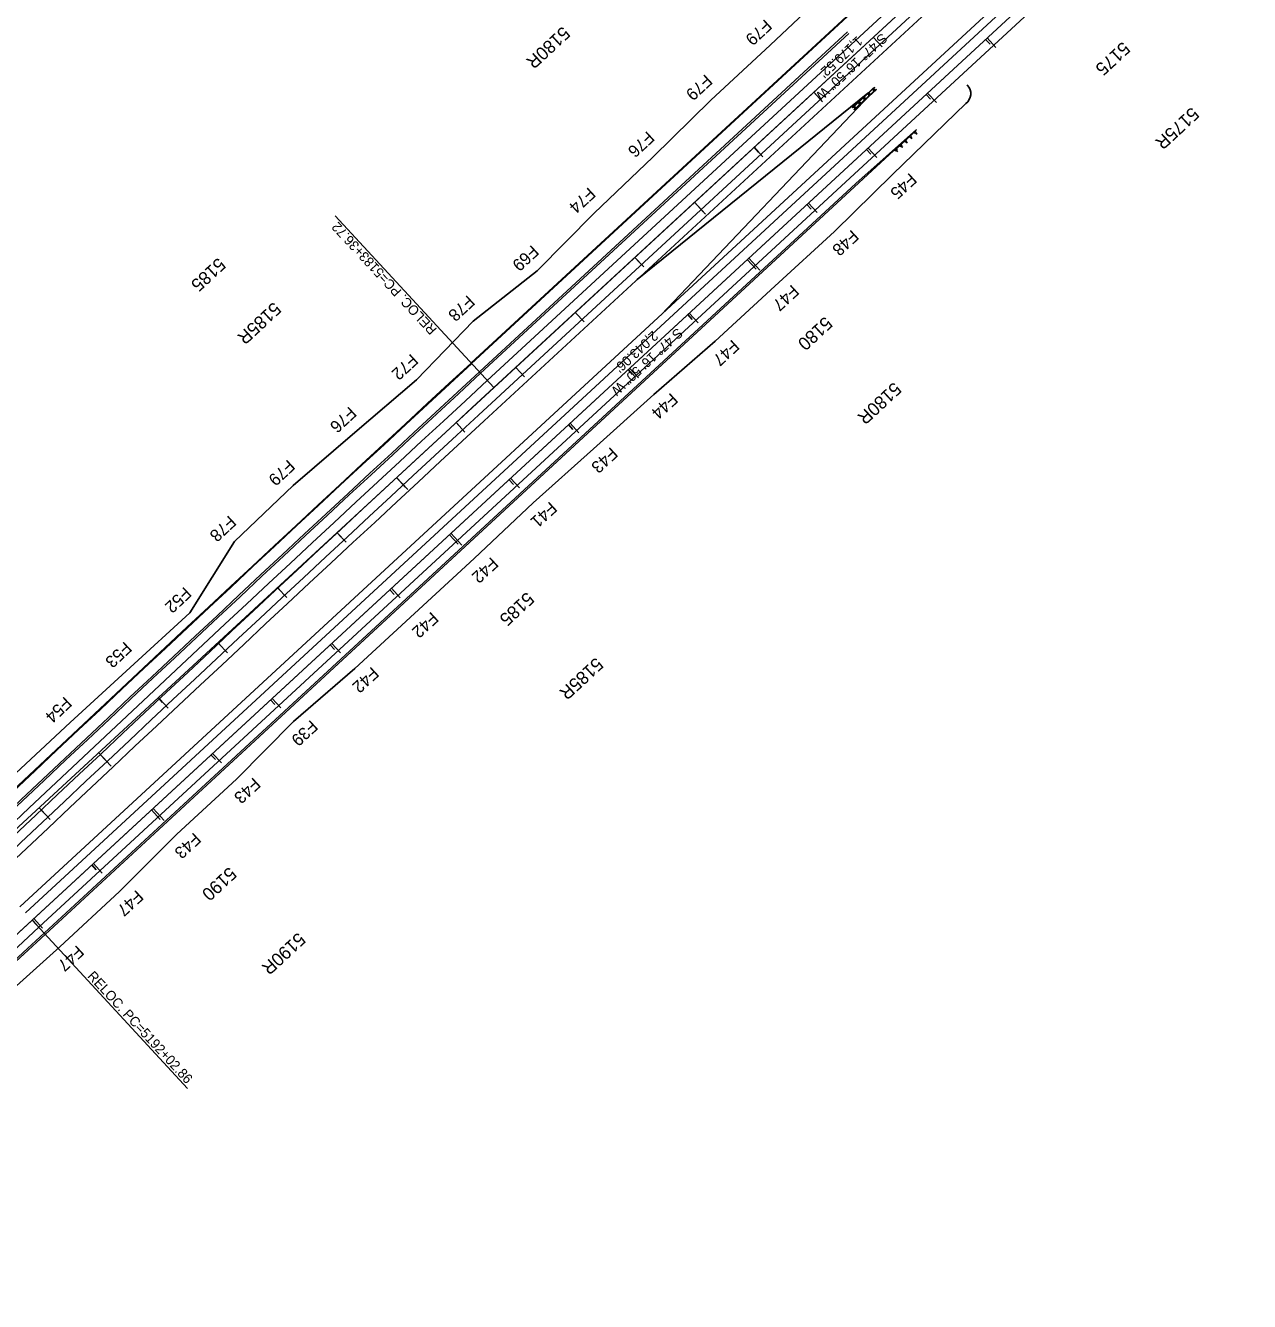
# Model space of a CAD drawing. Extents: x 2160877 to 2175861, y 601747 to 617724.
# Drawn here: x 2170763 to 2172272, y 611848 to 613421 of the extents above; entities that cross this region are included whole.
import ezdxf

# ---------------------------------------------------------------- set-up
doc = ezdxf.new("R2010")
doc.units = 0
for name, color, linetype in [('RD_HC_Cl', 7, 'Continuous'), ('RD_HC_CL_Rel', 7, 'Continuous'), ('RD_HC_Data_Rel', 7, 'Continuous'), ('RD_HC_Data_Tic', 7, 'Continuous'), ('RD_HC_Data_Tic_Rel', 7, 'Continuous'), ('RD_HC_TX_Rel_Sta50', 7, 'Continuous'), ('RD_HC_TX_Rel_StaOther', 7, 'Continuous'), ('RD_HC_TX_StaOther', 7, 'Continuous'), ('RD_PD_CstnLmt', 7, 'Continuous'), ('RD_PD_CstnLmt_TX', 7, 'Continuous'), ('RD_PD_Final_LnLine', 7, 'Continuous'), ('RD_PD_Final_TrvlWay', 7, 'Continuous'), ('RD_PD_GR', 7, 'Continuous'), ('RD_PD_MedBWall', 7, 'Continuous')]:
    doc.layers.add(name, color=color, linetype=linetype)

msp = doc.modelspace()

# ---------------------------------------------------------------- linework, layer by layer
at = {"layer": 'RD_HC_Cl'}
for p, q in [((2172207.3, 613775.1), (2163672.2, 605893.8)), ((2172272.5, 613704.6), (2163737.4, 605823.3))]:
    msp.add_line(p, q, dxfattribs=at)
at = {"layer": 'RD_HC_CL_Rel'}
for p, q in [((2172207.3, 613775.1), (2171340.7, 612974.9)), ((2172272.5, 613704.6), (2170771.4, 612318.6))]:
    msp.add_line(p, q, dxfattribs=at)
for centre, radius in [((2222221.5, 557873.6), 75000), ((2219616.9, 559421.3), 72000)]:
    msp.add_arc(centre, radius, 132.719474, 134.517591, dxfattribs=at)
at = {"layer": 'RD_HC_Data_Rel'}
for p, q in [((2171340.7, 612974.9), (2171145.2, 613186.7)), ((2170771.4, 612318.6), (2170963.2, 612110.9))]:
    msp.add_line(p, q, dxfattribs=at)
at = {"layer": 'RD_HC_Data_Tic'}
for p, q in [((2171808.5, 613406.9), (2171814, 613401)), ((2171947.1, 613404.2), (2171952.6, 613398.3)), ((2171735.1, 613339.1), (2171740.5, 613333.2)), ((2171873.7, 613336.4), (2171879.1, 613330.5)), ((2171661.6, 613271.2), (2171667, 613265.3)), ((2171800.2, 613268.5), (2171805.6, 613262.7)), ((2171588.1, 613203.4), (2171599, 613191.6)), ((2171726.7, 613200.7), (2171732.2, 613194.8)), ((2171514.7, 613135.5), (2171520.1, 613129.7)), ((2171653.3, 613132.8), (2171664.1, 613121.1)), ((2171441.2, 613067.7), (2171446.6, 613061.8)), ((2171579.8, 613065), (2171585.2, 613059.1)), ((2171367.7, 612999.9), (2171373.2, 612994)), ((2171506.3, 612997.2), (2171511.8, 612991.3)), ((2171294.3, 612932), (2171299.7, 612926.1)), ((2171432.9, 612929.3), (2171438.3, 612923.4)), ((2171220.8, 612864.2), (2171231.6, 612852.4)), ((2171359.4, 612861.5), (2171364.8, 612855.6)), ((2171147.3, 612796.3), (2171152.7, 612790.5)), ((2171285.9, 612793.6), (2171296.8, 612781.9)), ((2171073.9, 612728.5), (2171079.3, 612722.6)), ((2171212.4, 612725.8), (2171217.9, 612719.9)), ((2171000.4, 612660.7), (2171005.8, 612654.8)), ((2171139, 612658), (2171144.4, 612652.1)), ((2170926.9, 612592.8), (2170932.3, 612586.9)), ((2171065.5, 612590.1), (2171070.9, 612584.2)), ((2170853.4, 612525), (2170864.3, 612513.2)), ((2170992, 612522.3), (2170997.5, 612516.4)), ((2170780, 612457.1), (2170785.4, 612451.3)), ((2170918.6, 612454.4), (2170929.4, 612442.7)), ((2170845.1, 612386.6), (2170850.5, 612380.7)), ((2170771.6, 612318.8), (2170777.1, 612312.9))]:
    msp.add_line(p, q, dxfattribs=at)
at = {"layer": 'RD_HC_Data_Tic_Rel'}
for p, q in [((2171808.5, 613406.9), (2171819.4, 613395.1)), ((2171949, 613406), (2171959.9, 613394.2)), ((2171735.1, 613339.1), (2171745.9, 613327.3)), ((2171875.6, 613338.1), (2171886.4, 613326.4)), ((2171661.6, 613271.2), (2171672.5, 613259.5)), ((2171802.1, 613270.3), (2171813, 613258.5)), ((2171588.1, 613203.4), (2171601.7, 613188.7)), ((2171728.6, 613202.5), (2171739.5, 613190.7)), ((2171514.7, 613135.5), (2171525.5, 613123.8)), ((2171655.2, 613134.6), (2171668.7, 613119.9)), ((2171441.2, 613067.7), (2171452.1, 613055.9)), ((2171581.7, 613066.8), (2171592.6, 613055)), ((2171367.7, 612999.9), (2171378.6, 612988.1)), ((2171508.2, 612998.9), (2171519.1, 612987.2)), ((2171294.3, 612932), (2171305.1, 612920.2)), ((2171434.8, 612931.1), (2171445.6, 612919.3)), ((2171220.9, 612864), (2171234.5, 612849.4)), ((2171361.3, 612863.2), (2171372.2, 612851.5)), ((2171147.6, 612796), (2171158.5, 612784.3)), ((2171287.8, 612795.4), (2171301.4, 612780.7)), ((2171074.5, 612727.8), (2171085.4, 612716.1)), ((2171214.4, 612727.6), (2171225.2, 612715.8)), ((2171001.4, 612659.6), (2171012.3, 612647.9)), ((2171140.9, 612659.7), (2171151.7, 612648)), ((2170928.4, 612591.3), (2170939.3, 612579.6)), ((2171067.4, 612591.9), (2171078.3, 612580.1)), ((2170855.4, 612522.8), (2170869.1, 612508.2)), ((2170994, 612524), (2171004.8, 612512.3)), ((2170782.6, 612454.3), (2170793.6, 612442.6)), ((2170920.5, 612456.2), (2170934.1, 612441.5)), ((2170847, 612388.4), (2170857.9, 612376.6)), ((2170773.5, 612320.5), (2170784.4, 612308.8))]:
    msp.add_line(p, q, dxfattribs=at)
at = {"layer": 'RD_PD_CstnLmt'}
for p, q in [((2171754.2, 613465.7), (2171681.6, 613397)), ((2171681.6, 613397), (2171608.1, 613329.1)), ((2171924.2, 613348.1), (2171924.8, 613347.4)), ((2171608.1, 613329.1), (2171536.7, 613259)), ((2171832.4, 613237.5), (2171922.9, 613325.2)), ((2171536.7, 613259), (2171464.3, 613190.1)), ((2171832.4, 613237.5), (2171760.9, 613167.5)), ((2171464.3, 613190.1), (2171394.1, 613118.7)), ((2171760.9, 613167.5), (2171687.3, 613099.8)), ((2171394.1, 613118.7), (2171315.1, 613056.8)), ((2171687.3, 613099.8), (2171613.7, 613032.1)), ((2171315.1, 613056.8), (2171245.5, 612984.7)), ((2171613.7, 613032.1), (2171538.1, 612966.6)), ((2171245.5, 612984.7), (2171169.4, 612919.6)), ((2171538.1, 612966.6), (2171463.8, 612899.6)), ((2171169.4, 612919.6), (2171093.5, 612854.2)), ((2171463.8, 612899.6), (2171389.4, 612832.8)), ((2171093.5, 612854.2), (2171021, 612785.2)), ((2171389.4, 612832.8), (2171316.6, 612764.2)), ((2171021, 612785.2), (2170966, 612697.4)), ((2171316.6, 612764.2), (2171242.9, 612696.6)), ((2170966, 612697.4), (2170892.2, 612629.8)), ((2171242.9, 612696.6), (2171169.4, 612628.9)), ((2170892.2, 612629.8), (2170818.5, 612562.2)), ((2171169.4, 612628.9), (2171093.9, 612563.2)), ((2170818.5, 612562.2), (2170745.3, 612493.8)), ((2171093.9, 612563.2), (2171023.3, 612492.3)), ((2171023.3, 612492.3), (2170949.9, 612424.4)), ((2170949.9, 612424.4), (2170879, 612353.7)), ((2170879, 612353.7), (2170805.7, 612285.7)), ((2170805.7, 612285.7), (2170731.3, 612218.9))]:
    msp.add_line(p, q, dxfattribs=at)
msp.add_arc((2171913.8, 613337.2), 15, 307.2254, 42.7195, dxfattribs=at)
at = {"layer": 'RD_PD_Final_LnLine'}
for p, q in [((2172199.2, 613784), (2171332.6, 612983.8)), ((2172215.5, 613766.3), (2171348.9, 612966.1)), ((2172264.3, 613713.4), (2170763.3, 612327.4)), ((2172224.1, 613643.7), (2170779.6, 612309.8)), ((2171802, 613337.9), (2171517.6, 613108.3)), ((2171804.3, 613335.4), (2171547.4, 613065))]:
    msp.add_line(p, q, dxfattribs=at)
for centre, radius in [((2222221.5, 557873.6), 75012), ((2222221.5, 557873.6), 74988), ((2219616.9, 559421.3), 71988)]:
    msp.add_arc(centre, radius, 132.719474, 134.517591, dxfattribs=at)
at = {"layer": 'RD_PD_Final_TrvlWay'}
for p, q in [((2172222.2, 613759), (2171355.7, 612958.8)), ((2172257.5, 613720.8), (2170756.5, 612334.7)), ((2171776.7, 613413.4), (2171322.9, 612994.3)), ((2171778.3, 613411.6), (2171324.5, 612992.6)), ((2171787.2, 613226.6), (2171862, 613293)), ((2171787.2, 613226.6), (2170786.4, 612302.4))]:
    msp.add_line(p, q, dxfattribs=at)
for centre, radius in [((2222220.1, 557875.1), 75024.3), ((2222220.1, 557875.1), 75022), ((2222221.5, 557873.6), 74978), ((2219616.9, 559421.3), 71978)]:
    msp.add_arc(centre, radius, 132.719474, 134.517591, dxfattribs=at)
at = {"layer": 'RD_PD_GR'}
for p, q in [((2171809.9, 613345.3), (2171782.7, 613320.2)), ((2171783, 613319.8), (2171810.2, 613344.9)), ((2171784.9, 613317.9), (2171812, 613343)), ((2171812.4, 613342.6), (2171785.2, 613317.5)), ((2171807.2, 613343), (2171808.5, 613344.2)), ((2171807.6, 613342.6), (2171808.9, 613343.7)), ((2171809, 613341.1), (2171807.6, 613342.6)), ((2171808.7, 613342.7), (2171807.9, 613343.6)), ((2171809.4, 613343.2), (2171808.1, 613342.1)), ((2171808.1, 613342.1), (2171809.4, 613340.6)), ((2171808.9, 613343.7), (2171810.3, 613342.3)), ((2171810.3, 613342.3), (2171809, 613341.1)), ((2171810.7, 613341.8), (2171809.4, 613343.2)), ((2171809.4, 613340.6), (2171810.7, 613341.8)), ((2171809.6, 613341.7), (2171810.5, 613340.8)), ((2171809.8, 613340.2), (2171811.1, 613341.3)), ((2171810.2, 613344.9), (2171809.9, 613345.3)), ((2171812, 613343), (2171812.4, 613342.6)), ((2171787.7, 613324.1), (2171787.4, 613324.5)), ((2171789.6, 613326.7), (2171790.9, 613327.9)), ((2171790, 613326.3), (2171791.3, 613327.5)), ((2171791.4, 613324.8), (2171790, 613326.3)), ((2171791.1, 613326.4), (2171790.3, 613327.3)), ((2171791.7, 613327), (2171790.5, 613325.8)), ((2171790.5, 613325.8), (2171791.8, 613324.3)), ((2171791.3, 613327.5), (2171792.6, 613326)), ((2171792.6, 613326), (2171791.4, 613324.8)), ((2171793.1, 613325.5), (2171791.7, 613327)), ((2171791.8, 613324.3), (2171793.1, 613325.5)), ((2171792, 613325.4), (2171792.9, 613324.5)), ((2171792.2, 613323.9), (2171793.5, 613325.1)), ((2171795.5, 613332.1), (2171796.8, 613333.3)), ((2171795.9, 613331.7), (2171797.2, 613332.9)), ((2171797.2, 613330.2), (2171795.9, 613331.7)), ((2171797, 613331.8), (2171796.1, 613332.7)), ((2171797.6, 613332.4), (2171796.3, 613331.2)), ((2171796.3, 613331.2), (2171797.7, 613329.7)), ((2171797.2, 613332.9), (2171798.5, 613331.4)), ((2171798.5, 613331.4), (2171797.2, 613330.2)), ((2171799, 613330.9), (2171797.6, 613332.4)), ((2171797.7, 613329.7), (2171799, 613330.9)), ((2171797.9, 613330.8), (2171798.7, 613329.9)), ((2171798.1, 613329.3), (2171799.4, 613330.5)), ((2171801.4, 613337.6), (2171802.6, 613338.7)), ((2171801.8, 613337.1), (2171803, 613338.3)), ((2171803.1, 613335.7), (2171801.8, 613337.1)), ((2171802.9, 613337.2), (2171802, 613338.1)), ((2171803.5, 613337.8), (2171802.2, 613336.6)), ((2171802.2, 613336.6), (2171803.6, 613335.2)), ((2171803, 613338.3), (2171804.4, 613336.8)), ((2171804.4, 613336.8), (2171803.1, 613335.7)), ((2171804.9, 613336.4), (2171803.5, 613337.8)), ((2171803.6, 613335.2), (2171804.9, 613336.4)), ((2171803.8, 613336.2), (2171804.6, 613335.3)), ((2171804, 613334.7), (2171805.3, 613335.9)), ((2171782.7, 613320.2), (2171783, 613319.8)), ((2171783.7, 613321.3), (2171785, 613322.5)), ((2171784.1, 613320.8), (2171785.4, 613322)), ((2171785.5, 613319.4), (2171784.1, 613320.8)), ((2171785.2, 613320.9), (2171784.4, 613321.9)), ((2171785.9, 613321.5), (2171784.6, 613320.4)), ((2171784.6, 613320.4), (2171785.9, 613318.9)), ((2171785.2, 613317.5), (2171784.9, 613317.9)), ((2171785.4, 613322), (2171786.8, 613320.6)), ((2171786.8, 613320.6), (2171785.5, 613319.4)), ((2171787.2, 613320.1), (2171785.9, 613321.5)), ((2171785.9, 613318.9), (2171787.2, 613320.1)), ((2171786.1, 613320), (2171787, 613319)), ((2171786.3, 613318.5), (2171787.6, 613319.6)), ((2171789.5, 613322.2), (2171789.9, 613321.8)), ((2171861.2, 613292.3), (2171834.1, 613267.2)), ((2171834.4, 613266.9), (2171861.6, 613292)), ((2171861.6, 613292), (2171861.2, 613292.3)), ((2171847.2, 613278.7), (2171848.5, 613279.9)), ((2171848.6, 613277.3), (2171847.2, 613278.7)), ((2171848.5, 613279.9), (2171849.9, 613278.4)), ((2171849.9, 613278.4), (2171848.6, 613277.3)), ((2171849.2, 613277.8), (2171850.1, 613276.9)), ((2171849.4, 613276.3), (2171850.7, 613277.5)), ((2171853.1, 613284.2), (2171854.4, 613285.3)), ((2171854.5, 613282.7), (2171853.1, 613284.2)), ((2171854.4, 613285.3), (2171855.7, 613283.9)), ((2171855.7, 613283.9), (2171854.5, 613282.7)), ((2171855.1, 613283.3), (2171856, 613282.4)), ((2171855.3, 613281.8), (2171856.6, 613283)), ((2171859, 613289.6), (2171860.3, 613290.8)), ((2171860.3, 613288.1), (2171859, 613289.6)), ((2171860.3, 613290.8), (2171861.6, 613289.3)), ((2171861.6, 613289.3), (2171860.3, 613288.1)), ((2171861, 613288.7), (2171861.8, 613287.8)), ((2171861.2, 613287.2), (2171862.5, 613288.4)), ((2170787.7, 612300.9), (2171834.1, 613267.2)), ((2171834.1, 613267.2), (2171834.4, 613266.9)), ((2171835.5, 613267.9), (2171836.8, 613269.1)), ((2171836.8, 613266.4), (2171835.5, 613267.9)), ((2171836.8, 613269.1), (2171838.1, 613267.6)), ((2171838.1, 613267.6), (2171836.8, 613266.4)), ((2171837.5, 613267), (2171838.3, 613266.1)), ((2171837.7, 613265.5), (2171839, 613266.7)), ((2171839.1, 613271.2), (2171838.7, 613271.5)), ((2171841.4, 613273.3), (2171842.6, 613274.5)), ((2171842.7, 613271.8), (2171841.4, 613273.3)), ((2171842.6, 613274.5), (2171844, 613273)), ((2171844, 613273), (2171842.7, 613271.8)), ((2171843.4, 613272.4), (2171844.2, 613271.5)), ((2171843.6, 613270.9), (2171844.8, 613272.1))]:
    msp.add_line(p, q, dxfattribs=at)
msp.add_arc((2219616.9, 559421.3), 71976, 132.719474, 134.517591, dxfattribs=at)
at = {"layer": 'RD_PD_MedBWall'}
for p, q in [((2172075.1, 613709.3), (2171312.7, 613005.3)), ((2172075.8, 613708.6), (2171313.4, 613004.6))]:
    msp.add_line(p, q, dxfattribs=at)
for radius in [75039.3, 75038.3]:
    msp.add_arc((2222220.1, 557875.1), radius, 132.719474, 134.517591, dxfattribs=at)

# ---------------------------------------------------------------- texts
at = {"layer": 'RD_HC_Data_Rel'}
for s, rotation, p in [('RELOC. PC=5183+36.72', 132.7195, (2171271.4, 613047.1)), ('RELOC. PC=5192+02.86', 312.7195, (2170838.9, 612248.9))]:
    msp.add_text(s, height=12, rotation=rotation, dxfattribs=at).set_placement(p)
at = {"layer": 'RD_HC_TX_Rel_Sta50'}
for s, rotation, p in [('5180R', 222.7195, (2171425.6, 613421.1)), ('5175R', 222.7195, (2172201.2, 613321.6)), ('5185R', 222.8442, (2171069.3, 613081.3)), ('5180R', 222.7195, (2171834.1, 612982.6)), ('5185R', 222.7195, (2171466.5, 612643.2)), ('5190R', 222.7195, (2171099.4, 612304.2))]:
    msp.add_text(s, height=16, rotation=rotation, dxfattribs=at).set_placement(p)
at = {"layer": 'RD_HC_TX_Rel_StaOther'}
for s, p in [('S 47%%d 16\' 50" W', (2171819.1, 613412.6)), ("1,179.52'", (2171788.7, 613409)), ('S 47%%d 16\' 50" W', (2171567, 613049.2)), ("2,043.06'", (2171536.6, 613045.6))]:
    msp.add_text(s, height=12, rotation=222.7195, dxfattribs=at).set_placement(p)
at = {"layer": 'RD_HC_TX_StaOther'}
for s, p in [('5175', (2172116.1, 613402.3)), ('5185', (2171000.9, 613136)), ('5180', (2171749.1, 613063.5)), ('5185', (2171381.4, 612723.9)), ('5190', (2171014.4, 612385))]:
    msp.add_text(s, height=16, rotation=222.7195, dxfattribs=at).set_placement(p)
at = {"layer": 'RD_PD_CstnLmt_TX'}
for s, rotation, p in [('F79', 222.7195, (2171675.1, 613429.9)), ('F79', 222.7195, (2171601.6, 613362)), ('F76', 222.7195, (2171530.1, 613291.9)), ('F45', 222.7195, (2171853.6, 613240.4)), ('F74', 222.7195, (2171457.6, 613222.8)), ('F48', 222.7195, (2171782.1, 613170.4)), ('F69', 222.7195, (2171387.6, 613151.6)), ('F78', 222.7195, (2171308.6, 613089.7)), ('F47', 222.7195, (2171708.4, 613102.6)), ('F47', 222.7195, (2171634.8, 613034.9)), ('F72', 222.7678, (2171238.8, 613017.4)), ('F44', 222.7195, (2171559.1, 612969.3)), ('F76', 222.8442, (2171162.7, 612952.4)), ('F43', 222.7195, (2171485, 612902.5)), ('F79', 222.9206, (2171086.9, 612887.1)), ('F41', 222.7195, (2171410.1, 612835.2)), ('F78', 222.997, (2171014.4, 612818.1)), ('F42', 222.7195, (2171337.6, 612766.9)), ('F52', 223.0734, (2170959.2, 612730.2)), ('F42', 222.7195, (2171263.9, 612699.4)), ('F53', 223.1498, (2170885.6, 612662.7)), ('F42', 222.7195, (2171190.4, 612631.6)), ('F54', 223.2262, (2170811.6, 612594.9)), ('F39', 222.7195, (2171115.1, 612566.1)), ('F43', 222.7195, (2171044.5, 612495.2)), ('F43', 222.7195, (2170971.1, 612427.3)), ('F47', 222.7195, (2170900.1, 612356.5)), ('F47', 222.7195, (2170826.8, 612288.5))]:
    msp.add_text(s, height=15, rotation=rotation, dxfattribs=at).set_placement(p)

doc.saveas('drawing.dxf')
